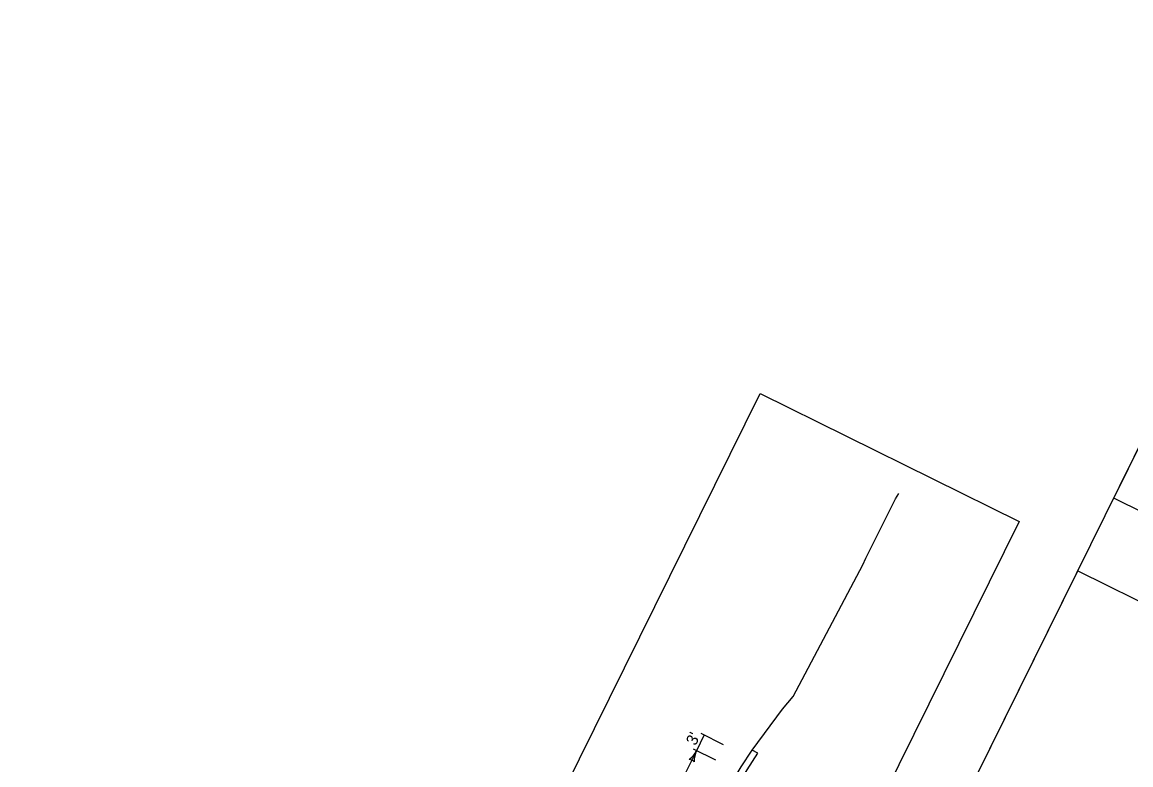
# Model space of a CAD drawing. Extents: x 14104283 to 14129344, y 8637090 to 8673339.
# Drawn here: x 14117870 to 14118644, y 8668759 to 8669277 of the extents above; entities that cross this region are included whole.
import ezdxf

# ---------------------------------------------------------------- set-up
doc = ezdxf.new("R2010")
doc.units = 0
for name, color, linetype in [('dsnCellElements', 7, 'Continuous'), ('dsnNonPlotable', 7, 'Continuous'), ('dsnTextFinalPlan', 7, 'Continuous'), ('dsnTextOverlapEven', 7, 'Continuous'), ('TC_SubstrataExistingPavement', 7, 'Continuous'), ('Terrain', 7, 'Continuous')]:
    doc.layers.add(name, color=color, linetype=linetype)

# ---------------------------------------------------------------- blocks, each defined once
blk = doc.blocks.new('LT')
at = {"layer": 'dsnCellElements'}
for centre, radius, start, end in [((-3.56, 0), 1.64, 342.2666, 17.7333), ((0, 4.25), 4.25, 241.9275, 270), ((0, -4.25), 4.25, 90, 118.0725)]:
    blk.add_arc(centre, radius, start, end, dxfattribs=at)

msp = doc.modelspace()

# ---------------------------------------------------------------- linework, layer by layer
at = {"layer": 'dsnNonPlotable'}
for points in [[(14118631.64, 8668945.1), (14119326.37, 8670350.23), (14120231.75, 8669902.59), (14119537.02, 8668497.46)], [(14118092.03, 8667853.71), (14118786.76, 8669258.84), (14119692.14, 8668811.2), (14118997.41, 8667406.07)]]:
    msp.add_lwpolyline(points, close=True, dxfattribs=at)
at = {"layer": 'dsnTextFinalPlan'}
for p, q in [((14118343.62, 8668781.13), (14118359.28, 8668773.39)), ((14118340.75, 8668769.16), (14118346.07, 8668779.92)), ((14118319.48, 8668726.13), (14118340.75, 8668769.16)), ((14118338.3, 8668770.37), (14118353.96, 8668762.63))]:
    msp.add_line(p, q, dxfattribs=at)
for points in [[(14117870.36, 8667977.42), (14118384.92, 8669018.16), (14118565.56, 8668928.85), (14118050.99, 8667888.12)], [(14118092.03, 8667853.71), (14118606.59, 8668894.44), (14118787.23, 8668805.14), (14118272.66, 8667764.4)]]:
    msp.add_lwpolyline(points, close=True, dxfattribs=at)
at = {"layer": 'dsnTextOverlapEven'}
msp.add_lwpolyline([(14117870.36, 8667977.42), (14118384.92, 8669018.16), (14118565.56, 8668928.85), (14118050.99, 8667888.12)], close=True, dxfattribs=at)
at = {"layer": 'TC_SubstrataExistingPavement'}
msp.add_lwpolyline([(14118359.1, 8668736.38), (14118363.29, 8668734.31), (14118375.98, 8668755.74), (14118383.52, 8668767.37), (14118379.34, 8668769.44)], dxfattribs=at)
at = {"layer": 'Terrain'}
for points in [[(14118456.58, 8668898.64), (14118458.74, 8668903.28), (14118479.41, 8668944.73), (14118481.73, 8668948.36)], [(14118312.3, 8668644.82), (14118315.38, 8668650.41), (14118318.4, 8668656.85), (14118336.09, 8668694.53), (14118351.32, 8668721.95), (14118359.1, 8668736.38), (14118371.8, 8668757.81), (14118379.34, 8668769.44), (14118400.6, 8668797.95), (14118408.04, 8668806.8), (14118456.58, 8668898.64)]]:
    msp.add_lwpolyline(points, dxfattribs=at)

# ---------------------------------------------------------------- block references
at = {"layer": 'dsnTextFinalPlan', "xscale": 3.942400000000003, "yscale": 3.9424000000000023, "rotation": 63.69110745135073}
msp.add_blockref('LT', (14118340.75, 8668769.16), dxfattribs=at)

# ---------------------------------------------------------------- texts
at = {"layer": 'dsnTextFinalPlan'}
msp.add_text("3'", height=8, rotation=63.69111, dxfattribs=at).set_placement((14118339.99, 8668772.1))

doc.saveas('drawing.dxf')
